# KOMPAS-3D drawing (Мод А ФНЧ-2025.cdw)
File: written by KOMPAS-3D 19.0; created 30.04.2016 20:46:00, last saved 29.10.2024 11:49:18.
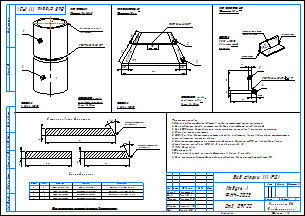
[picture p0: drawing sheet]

Sheet 1: A3, landscape

Document properties: Автор: Владимир; Организация: СПО; Масса: 0; sheetsnumber: 2; Полное имя файла: C:\Users\WELDER_72\OneDrive\Desktop\Мод А ФНЧ-2025.cdw

Title block, sheet 1: Наименование: Модуль А / ФНЧ-2025; designation: Вид сварки 111 (РД); Материал: Ст3, 09Г2С; Количество листов документа: 1; organisation: Чемпионат ПМ / "Профессионалы"; Форматы листов документа: A3; stored path: C:\Users\Владимир\Desktop\22.cdw; Разработал: Калашников; Проверил: Голов С. А.; Т. контр.: Порошин Г. Ю.; Н. контр.: Красилов А. С.; Утвердил: Дюкова С. В.

Views: Вид сварки 111 (РД), Вид сварки 111 (РД)-
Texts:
  Defpoints
  Title Block
  CFS-SHT
  LOGO
  Все размеры на чертеже указаны в миллиметрах
  Технические условия:
  1. Сборка соединений производится в любом пространственном положении;
  2. Все соединения труб и пластин необходимо проклеймить перед сваркой;
  3. Все КСС должны быть сварены с расположением маркировки в указанном положении;
  4. Сварка на спуск запрещена;
  5. КСС А1 - А3 не допускается очистка лицевых и обратных валиков абразивным инструментом
  после завершения процесса сварки;
  6. Выполнить стоп-точки по центру соединения с допуском   37,5 мм в последнем валике
  облицовочного прохода на КСС А2, А3 и первом проходе А3;
  7. XX = Маркировка.
  КСС пластин A3:
  1. Сварка углового шва на лицевой стороне, в 2 слоя, 3 прохода;
  2. Угол сопряжения деталей при сборке соединения должен соответствовать 90 .
  Величина притупления
  на ваш выбор
  Деталировочный чертеж
  КСС ПЛАСТИН A3:
  Tолщина: 10 мм.
  ОЦЕНКА:
  1. ВИК - 100%
  2. Разрушающий
  контроль
  Обратная
  сторона
  Место прихватки
  Место прихватки по центру
  длина, не более 25 мм
  КСС ПЛАСТИН A2:
  Толщина: 10 мм.
  ВНИМАНИЕ: кол-во
  прихваток - две,
  длина до 15 мм.
  Кол-во
  Описание
  Сталь марки 09Г2С
  Труба   114х8-120
  Токарная обработка 30 град.
  Сталь марки Ст3
  Пластина 10х100х250
  Фрезерная обработка 25 град.
  Пластина 10х75х250
  Фрезерная обработка 90 град.
  КСС ТРУБ A1:
  Размер: 114х8-120
  прихваток - четыре,
  длина до 15мм.
  Удерживать на 12 часов
  (не вращать)
  Не оценивается
  ГОСТ 5264-80-Т1- 8
  ГОСТ 16037-80 С17
  ГОСТ 5264-80 С17
  CHAIN_RGB_0_0_0_SC_40_THICK_0.18
  CHAIN_RGB_0_0_0_SC_4.7_THICK_0.18
  POLYLINE_STYLE_0.18_RGB_0_0_0
  POLYLINE_STYLE_0.42_RGB_0_0_0
  POLYLINE_STYLE_0.42_RGB_255_0_0
  POLYLINE_STYLE_0.42_RGB_255_255_0
  POLYLINE_STYLE_0.42_RGB_63_0_255
  POLYLINE_STYLE_0.42_RGB_0_127_31
Dimensions and other numbers on the sheet: 30 3; 40 1; 75; 10; 100; 4; 3; 1; 2; 250; 20; 25 2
